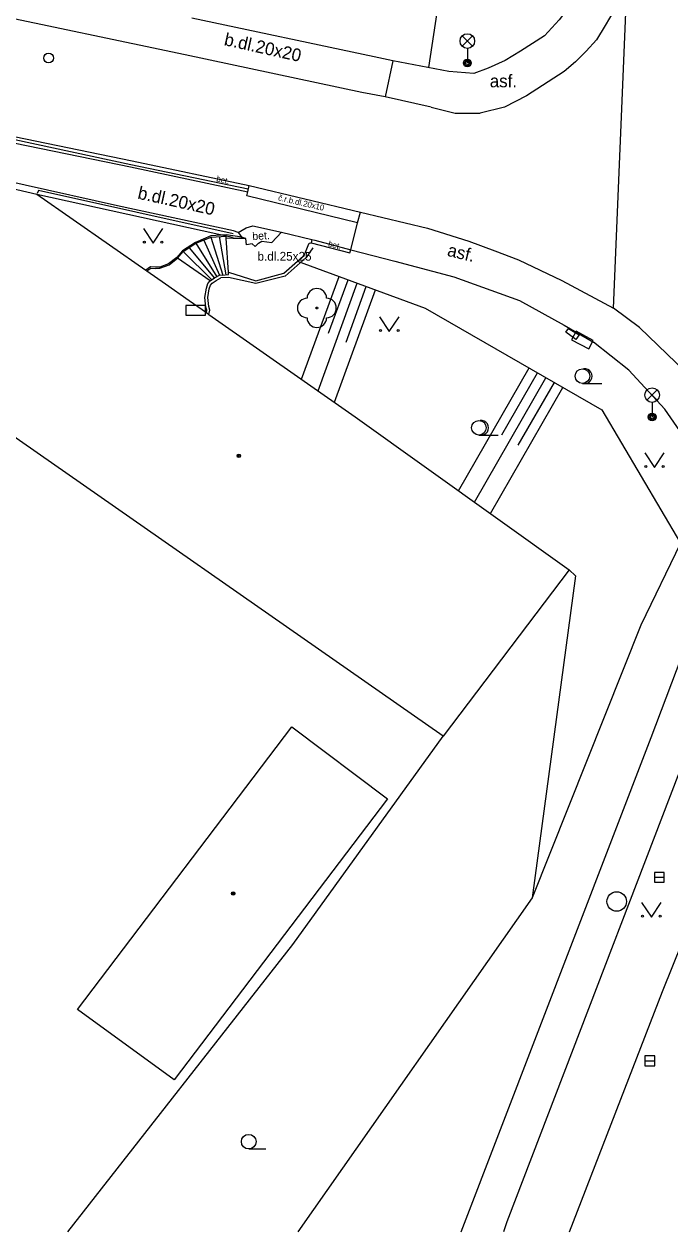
# Model space of a CAD drawing. Extents: x -595546 to -593986, y -1160845 to -1159202.
# Drawn here: x -594705.7 to -594672.6, y -1160843.2 to -1160781.2 of the extents above; entities that cross this region are included whole.
import ezdxf

# ---------------------------------------------------------------- set-up
doc = ezdxf.new("R2010")
doc.units = 0
for name, color, linetype in [('DOP - budovy nerozlisene - VP', 7, 'Continuous'), ('DOP - rozhrani ploch obecne', 7, 'Continuous'), ('Level 22', 7, 'Continuous'), ('Level 24', 7, 'Continuous'), ('Level 27', 7, 'Continuous'), ('Level 28', 7, 'Continuous'), ('Level 33', 7, 'Continuous'), ('Level 36', 7, 'Continuous'), ('Level 39', 7, 'Continuous'), ('silnoproud - povrch.  znaky a  RIS  skut. velikost', 7, 'Continuous'), ('Specificka linie pasportu komunikaci', 7, 'Continuous'), ('TM - budovy zdene_ betonove - VP', 7, 'Continuous'), ('TM - chodniky - VP', 7, 'Continuous'), ('TM - horni hrana svahu', 7, 'Continuous'), ('TM - komunikace - VP', 7, 'Continuous'), ('TM - plot drateny_ kovovy - VP', 7, 'Continuous'), ('TM - podezdivka plotu - VP', 7, 'Continuous'), ('TM - pomocna konstrukcni linie', 7, 'Continuous'), ('TM - popis povrchu', 7, 'Continuous'), ('TM - rozhrani mezi zpev. plochami mezi sebou - VP', 7, 'Continuous'), ('TM - rozhrani ploch obecne - VP', 7, 'Continuous'), ('TM - schody - VP', 7, 'Continuous'), ('TM - srafovani', 7, 'Continuous'), ('TM - zabradli - VP', 7, 'Continuous'), ('TM - zed operna - VP', 7, 'Continuous')]:
    doc.layers.add(name, color=color, linetype=linetype)

msp = doc.modelspace()

# ---------------------------------------------------------------- linework, layer by layer
at = {"layer": 'DOP - budovy nerozlisene - VP'}
for points in [[(-594702.99, -1160831.83), (-594691.98, -1160817.31)], [(-594691.98, -1160817.31), (-594687.07, -1160821.01)], [(-594687.07, -1160821.01), (-594698.03, -1160835.44)], [(-594698.03, -1160835.44), (-594702.99, -1160831.83)]]:
    msp.add_lwpolyline(points, dxfattribs=at)
at = {"layer": 'DOP - rozhrani ploch obecne'}
for points in [[(-594691.94, -1160828.49), (-594684.22, -1160817.79)], [(-594703.497, -1160843.241), (-594691.94, -1160828.49)]]:
    msp.add_lwpolyline(points, dxfattribs=at)
at = {"layer": 'Level 22'}
msp.add_circle((-594690.7, -1160795.81), 0.05, dxfattribs=at)
for centre, start, end in [((-594690.7, -1160795.31), 0, 180), ((-594691.2, -1160795.81), 90, 270), ((-594690.2, -1160795.81), 270, 90), ((-594690.7, -1160796.31), 180, 0)]:
    msp.add_arc(centre, 0.5, start, end, dxfattribs=at)
at = {"layer": 'Level 24'}
for points in [[(-594697.427, -1160796.178), (-594696.427, -1160796.178), (-594696.427, -1160795.678), (-594697.427, -1160795.678)], [(-594677.619, -1160797.447), (-594676.735, -1160797.915), (-594676.501, -1160797.473), (-594677.385, -1160797.005)]]:
    msp.add_lwpolyline(points, close=True, dxfattribs=at)
at = {"layer": 'Level 27'}
for p, q in [((-594673.36, -1160825.04), (-594672.86, -1160825.04)), ((-594673.85, -1160834.46), (-594673.35, -1160834.46))]:
    msp.add_line(p, q, dxfattribs=at)
for points in [[(-594673.36, -1160825.29), (-594672.86, -1160825.29), (-594672.86, -1160824.79), (-594673.36, -1160824.79)], [(-594673.85, -1160834.71), (-594673.35, -1160834.71), (-594673.35, -1160834.21), (-594673.85, -1160834.21)]]:
    msp.add_lwpolyline(points, close=True, dxfattribs=at)
msp.add_circle((-594675.3, -1160826.28), 0.5, dxfattribs=at)
at = {"layer": 'Level 28'}
msp.add_circle((-594704.48, -1160782.98), 0.25, dxfattribs=at)
at = {"layer": 'Level 33'}
for p, q in [((-594683.235, -1160782.37), (-594682.705, -1160781.84)), ((-594683.235, -1160781.84), (-594682.705, -1160782.37)), ((-594682.97, -1160782.48), (-594682.97, -1160783.23)), ((-594673.745, -1160800.55), (-594673.215, -1160800.02)), ((-594673.745, -1160800.02), (-594673.215, -1160800.55)), ((-594673.48, -1160800.66), (-594673.48, -1160801.41))]:
    msp.add_line(p, q, dxfattribs=at)
for centre, radius in [((-594682.97, -1160782.105), 0.375), ((-594682.97, -1160783.23), 0.2), ((-594682.97, -1160783.23), 0.145), ((-594682.97, -1160783.23), 0.0876), ((-594673.48, -1160800.285), 0.375), ((-594673.48, -1160801.41), 0.2), ((-594673.48, -1160801.41), 0.145), ((-594673.48, -1160801.41), 0.0876)]:
    msp.add_circle(centre, radius, dxfattribs=at)
at = {"layer": 'Level 36'}
for p, q in [((-594677.06, -1160799.685), (-594676.06, -1160799.685)), ((-594682.38, -1160802.335), (-594681.38, -1160802.335)), ((-594694.2, -1160838.985), (-594693.325, -1160838.985))]:
    msp.add_line(p, q, dxfattribs=at)
for points in [[(-594699.61, -1160791.73), (-594699.11, -1160792.48), (-594698.61, -1160791.73)], [(-594687.48, -1160796.27), (-594686.98, -1160797.02), (-594686.48, -1160796.27)], [(-594673.86, -1160803.25), (-594673.36, -1160804), (-594672.86, -1160803.25)], [(-594674.02, -1160826.33), (-594673.52, -1160827.08), (-594673.02, -1160826.33)]]:
    msp.add_lwpolyline(points, dxfattribs=at)
for centre, radius in [((-594699.56, -1160792.43), 0.05), ((-594698.661, -1160792.43), 0.05), ((-594687.43, -1160796.97), 0.05), ((-594686.531, -1160796.97), 0.05), ((-594677.06, -1160799.31), 0.375), ((-594682.38, -1160801.96), 0.375), ((-594673.81, -1160803.95), 0.05), ((-594672.911, -1160803.95), 0.05), ((-594673.97, -1160827.03), 0.05), ((-594673.071, -1160827.03), 0.05), ((-594694.2, -1160838.61), 0.375)]:
    msp.add_circle(centre, radius, dxfattribs=at)
for centre in [(-594676.935, -1160799.31), (-594682.255, -1160801.96)]:
    msp.add_arc(centre, 0.375, 260.40593, 99.59407, dxfattribs=at)
at = {"layer": 'Level 39'}
for centre, radius in [((-594694.71, -1160803.4), 0.09), ((-594694.71, -1160803.4), 0.0398), ((-594695, -1160825.87), 0.09), ((-594695, -1160825.87), 0.0398)]:
    msp.add_circle(centre, radius, dxfattribs=at)
at = {"layer": 'silnoproud - povrch.  znaky a  RIS  skut. velikost'}
msp.add_lwpolyline([(-594677.22, -1160797.19), (-594677.4, -1160797.42), (-594677.92, -1160797.06), (-594677.78, -1160796.86), (-594677.22, -1160797.19)], dxfattribs=at)
at = {"layer": 'Specificka linie pasportu komunikaci'}
msp.add_lwpolyline([(-594675.46, -1160795.82), (-594674.78, -1160779.4)], dxfattribs=at)
at = {"layer": 'TM - budovy zdene_ betonove - VP'}
for points in [[(-594706.91, -1160789.54), (-594705.09, -1160789.97)], [(-594705.09, -1160789.97), (-594699.49, -1160793.87), (-594699.44, -1160793.91)], [(-594699.44, -1160793.91), (-594698.48, -1160794.57)], [(-594698.48, -1160794.57), (-594697.26, -1160795.42), (-594696.37, -1160796.04)], [(-594696.37, -1160796.04), (-594696.24, -1160796.14), (-594688.74, -1160801.4), (-594677.74, -1160809.25)], [(-594684.22, -1160817.79), (-594709.11, -1160800.44)], [(-594677.74, -1160809.25), (-594684.22, -1160817.79)]]:
    msp.add_lwpolyline(points, dxfattribs=at)
at = {"layer": 'TM - chodniky - VP'}
for points in [[(-594677.57, -1160780.13), (-594678.26, -1160781.01), (-594679.01, -1160781.84), (-594680.24, -1160782.63)], [(-594687.75, -1160782.92), (-594697.12, -1160780.93)], [(-594680.24, -1160782.63), (-594681.03, -1160783.1), (-594681.91, -1160783.49)], [(-594686.79, -1160783.12), (-594687.75, -1160782.92)], [(-594683.93, -1160783.67), (-594686.79, -1160783.12)], [(-594682.63, -1160783.78), (-594683.93, -1160783.67)], [(-594681.91, -1160783.49), (-594682.63, -1160783.78)], [(-594694.75, -1160791.94), (-594694.33, -1160791.7)], [(-594694.33, -1160791.7), (-594693.98, -1160791.6)], [(-594693.98, -1160791.6), (-594692.52, -1160791.91)], [(-594692.52, -1160791.91), (-594690.95, -1160792.3)], [(-594690.95, -1160792.3), (-594690.81, -1160792.33)], [(-594690.81, -1160792.33), (-594688.96, -1160792.82)], [(-594688.96, -1160792.82), (-594686.7, -1160793.4)], [(-594686.7, -1160793.4), (-594683.66, -1160794.21)], [(-594683.66, -1160794.21), (-594680.29, -1160795.43)], [(-594680.29, -1160795.43), (-594678, -1160796.69)], [(-594678, -1160796.69), (-594676.49, -1160797.56)], [(-594674.67, -1160799.01), (-594676.49, -1160797.56)], [(-594672.82, -1160801), (-594674.67, -1160799.01)], [(-594671.4, -1160803.05), (-594672.82, -1160801)], [(-594669.62, -1160813.23), (-594680.94, -1160842.73)], [(-594673.53, -1160817.86), (-594671.69, -1160813.02)], [(-594683.291, -1160843.241), (-594673.53, -1160817.86)], [(-594680.94, -1160842.73), (-594681.117, -1160843.241)]]:
    msp.add_lwpolyline(points, dxfattribs=at)
at = {"layer": 'TM - horni hrana svahu'}
msp.add_lwpolyline([(-594691.7, -1160793.41), (-594685.13, -1160795.82), (-594676.07, -1160801.04), (-594672.03, -1160807.88), (-594674.06, -1160812.09)], dxfattribs=at)
at = {"layer": 'TM - komunikace - VP'}
for points in [[(-594674.78, -1160779.4), (-594675.9, -1160781.31)], [(-594697.47, -1160782.82), (-594707.9, -1160780.62)], [(-594675.9, -1160781.31), (-594676.34, -1160782.05)], [(-594676.34, -1160782.05), (-594676.86, -1160782.63), (-594677.41, -1160783.17), (-594678, -1160783.67)], [(-594688.39, -1160784.74), (-594697.47, -1160782.82)], [(-594678, -1160783.67), (-594679.94, -1160784.91)], [(-594687.2, -1160784.97), (-594688.39, -1160784.74)], [(-594684.83, -1160785.5), (-594687.2, -1160784.97)], [(-594679.94, -1160784.91), (-594681.07, -1160785.5), (-594682.31, -1160785.81)], [(-594684.83, -1160785.5), (-594683.59, -1160785.81)], [(-594710.08, -1160786.22), (-594700.18, -1160788.26)], [(-594683.59, -1160785.81), (-594682.55, -1160785.81), (-594682.31, -1160785.81)], [(-594700.18, -1160788.26), (-594694.17, -1160789.52)], [(-594694.17, -1160789.52), (-594688.46, -1160790.89)], [(-594688.46, -1160790.89), (-594685.02, -1160791.72)], [(-594685.02, -1160791.72), (-594682.9, -1160792.38)], [(-594682.9, -1160792.38), (-594681.56, -1160792.88), (-594680.34, -1160793.33)], [(-594680.34, -1160793.33), (-594678.12, -1160794.4)], [(-594678.12, -1160794.4), (-594675.46, -1160795.82)], [(-594674.13, -1160796.81), (-594675.46, -1160795.82)], [(-594670.84, -1160799.98), (-594674.13, -1160796.81)], [(-594672.95, -1160830.91), (-594667.81, -1160818.16)], [(-594677.729, -1160843.241), (-594672.95, -1160830.91)]]:
    msp.add_lwpolyline(points, dxfattribs=at)
at = {"layer": 'TM - plot drateny_ kovovy - VP'}
for points in [[(-594677.74, -1160809.25), (-594677.41, -1160809.56)], [(-594677.41, -1160809.56), (-594679.65, -1160826.1)], [(-594679.65, -1160826.1), (-594691.669, -1160843.241)]]:
    msp.add_lwpolyline(points, dxfattribs=at)
at = {"layer": 'TM - podezdivka plotu - VP'}
for points in [[(-594705.09, -1160789.97), (-594695.04, -1160792.18)], [(-594694.25, -1160789.84), (-594694.17, -1160789.52)], [(-594695.04, -1160792.18), (-594695, -1160792.24)]]:
    msp.add_lwpolyline(points, dxfattribs=at)
at = {"layer": 'TM - pomocna konstrukcni linie'}
msp.add_lwpolyline([(-594674.06, -1160812.09), (-594679.65, -1160826.1)], dxfattribs=at)
at = {"layer": 'TM - rozhrani mezi zpev. plochami mezi sebou - VP'}
for points in [[(-594686.79, -1160783.12), (-594687.2, -1160784.97)], [(-594694.3, -1160790.05), (-594694.25, -1160789.84)], [(-594694.3, -1160790.05), (-594694.25, -1160789.84)], [(-594688.61, -1160791.43), (-594694.3, -1160790.05)], [(-594688.61, -1160791.43), (-594688.46, -1160790.89)], [(-594688.96, -1160792.82), (-594688.61, -1160791.43)], [(-594690.95, -1160792.3), (-594690.99, -1160792.46)]]:
    msp.add_lwpolyline(points, dxfattribs=at)
at = {"layer": 'TM - rozhrani ploch obecne - VP'}
for points in [[(-594692.52, -1160791.91), (-594693.01, -1160792.44)], [(-594697.56, -1160792.91), (-594696.91, -1160792.49)], [(-594696.91, -1160792.49), (-594696.13, -1160792.17)], [(-594696.13, -1160792.17), (-594695.36, -1160792.12)], [(-594695.35, -1160792.23), (-594695.36, -1160792.12)], [(-594695.24, -1160793.97), (-594695.35, -1160792.23)], [(-594695, -1160792.24), (-594695.35, -1160792.23)], [(-594694.5, -1160792.25), (-594695, -1160792.24)], [(-594694.35, -1160792.25), (-594694.5, -1160792.25)], [(-594694.31, -1160792.56), (-594694.35, -1160792.25)], [(-594694.03, -1160792.52), (-594694.31, -1160792.56)], [(-594693.87, -1160792.66), (-594694.03, -1160792.52)], [(-594693.87, -1160792.66), (-594693.7, -1160792.48)], [(-594693.7, -1160792.48), (-594693.53, -1160792.38)], [(-594693.53, -1160792.38), (-594693.01, -1160792.44)], [(-594691.15, -1160792.61), (-594691.09, -1160792.48)], [(-594691.09, -1160792.48), (-594690.99, -1160792.46)], [(-594690.99, -1160792.46), (-594689, -1160792.98)], [(-594697.85, -1160793.26), (-594697.56, -1160792.91)], [(-594691.7, -1160793.41), (-594691.36, -1160793.12)], [(-594691.36, -1160793.12), (-594691.15, -1160792.61)], [(-594689, -1160792.98), (-594688.96, -1160792.82)], [(-594699.44, -1160793.91), (-594699.23, -1160793.76)], [(-594699.23, -1160793.76), (-594698.98, -1160793.78)], [(-594698.98, -1160793.78), (-594698.76, -1160793.77)], [(-594698.76, -1160793.77), (-594698.29, -1160793.6)], [(-594698.29, -1160793.6), (-594697.85, -1160793.26)], [(-594696.18, -1160794.42), (-594697.85, -1160793.26)], [(-594692.4, -1160794.03), (-594691.7, -1160793.41)], [(-594696.18, -1160794.42), (-594695.95, -1160794.27)], [(-594695.95, -1160794.27), (-594695.67, -1160794.11)], [(-594695.67, -1160794.11), (-594695.57, -1160794.13)], [(-594695.57, -1160794.13), (-594695.23, -1160794.09)], [(-594695.24, -1160793.97), (-594693.83, -1160794.41)], [(-594695.23, -1160794.09), (-594695.24, -1160793.97)], [(-594693.83, -1160794.41), (-594692.4, -1160794.03)], [(-594696.45, -1160795.27), (-594696.37, -1160794.79)], [(-594696.37, -1160794.79), (-594696.3, -1160794.56)], [(-594696.3, -1160794.56), (-594696.18, -1160794.42)], [(-594696.4, -1160795.76), (-594696.45, -1160795.27)], [(-594696.35, -1160795.93), (-594696.4, -1160795.76)], [(-594696.37, -1160796.04), (-594696.35, -1160795.93)]]:
    msp.add_lwpolyline(points, dxfattribs=at)
at = {"layer": 'TM - schody - VP'}
for points in [[(-594696.91, -1160792.49), (-594695.84, -1160794.21)], [(-594696.51, -1160792.32), (-594695.7, -1160794.13)], [(-594696.14, -1160792.17), (-594695.53, -1160794.13)], [(-594695.72, -1160792.14), (-594695.38, -1160794.11)], [(-594697.56, -1160792.91), (-594696.09, -1160794.36)], [(-594697.26, -1160792.72), (-594695.96, -1160794.28)]]:
    msp.add_lwpolyline(points, dxfattribs=at)
at = {"layer": 'TM - srafovani'}
for points in [[(-594684.08, -1160777.57), (-594684.96, -1160783.47)], [(-594691.49, -1160799.47), (-594689.56, -1160794.2)], [(-594690.1, -1160797.1), (-594689.09, -1160794.37)], [(-594690.64, -1160800.07), (-594688.63, -1160794.54)], [(-594689.8, -1160800.65), (-594687.69, -1160794.88)], [(-594689.2, -1160797.57), (-594688.16, -1160794.71)], [(-594683.43, -1160805.19), (-594679.8, -1160798.89)], [(-594681.2, -1160802.32), (-594679.37, -1160799.14)], [(-594682.61, -1160805.78), (-594678.94, -1160799.39)], [(-594681.79, -1160806.36), (-594678.07, -1160799.89)], [(-594680.36, -1160802.86), (-594678.5, -1160799.64)]]:
    msp.add_lwpolyline(points, dxfattribs=at)
at = {"layer": 'TM - zabradli - VP'}
for points in [[(-594710.2, -1160786.31), (-594700.25, -1160788.44)], [(-594700.25, -1160788.44), (-594694.22, -1160789.69)], [(-594705, -1160789.77), (-594705.06, -1160789.94)], [(-594695, -1160792), (-594705, -1160789.77)], [(-594694.55, -1160792.17), (-594695.36, -1160792.06), (-594696.14, -1160792.11), (-594696.94, -1160792.44), (-594697.6, -1160792.87), (-594697.89, -1160793.22), (-594698.32, -1160793.55), (-594698.77, -1160793.71), (-594698.98, -1160793.72), (-594699.25, -1160793.7), (-594699.49, -1160793.87)], [(-594694.36, -1160792.24), (-594694.55, -1160792.17)], [(-594690.9, -1160792.72), (-594691.25, -1160793.22), (-594692.33, -1160794.17)], [(-594696.24, -1160796.14), (-594696.2, -1160795.92), (-594696.25, -1160795.73), (-594696.3, -1160795.28), (-594696.23, -1160794.82), (-594696.17, -1160794.63), (-594696.08, -1160794.53), (-594695.87, -1160794.4), (-594695.63, -1160794.26)], [(-594692.33, -1160794.17), (-594693.83, -1160794.56), (-594695.24, -1160794.24), (-594695.63, -1160794.26)]]:
    msp.add_lwpolyline(points, dxfattribs=at)
at = {"layer": 'TM - zed operna - VP'}
for points in [[(-594710.21, -1160786.52), (-594700.28, -1160788.56)], [(-594700.94, -1160790.56), (-594715.18, -1160787.38)], [(-594700.28, -1160788.56), (-594694.25, -1160789.84)], [(-594694.98, -1160791.85), (-594700.94, -1160790.56)], [(-594694.75, -1160791.94), (-594694.98, -1160791.85)], [(-594694.7, -1160791.96), (-594694.75, -1160791.94)], [(-594694.5, -1160792.25), (-594694.7, -1160791.96)]]:
    msp.add_lwpolyline(points, dxfattribs=at)

# ---------------------------------------------------------------- texts
at = {"layer": 'TM - popis povrchu'}
for s, height, rotation, p in [('b.dl.20x20', 0.65, 347.46685, (-594695.5, -1160782.31)), ('bet.', 0.3, 348, (-594695.88, -1160789.31)), ('b.dl.20x20', 0.65, 347.46685, (-594699.94, -1160790.19)), ('č.r.b.dl.20x10', 0.3, 347, (-594692.71, -1160790.28)), ('bet.', 0.4, 3.70537, (-594694, -1160792.33)), ('bet.', 0.3, 345, (-594690.14, -1160792.64)), ('asf.', 0.65, 346.68392, (-594684.04, -1160793.13))]:
    msp.add_text(s, height=height, rotation=rotation, dxfattribs=at).set_placement(p)
for s, height, p in [('asf.', 0.65, (-594681.82, -1160784.48)), ('b.dl.25x25', 0.45, (-594693.75, -1160793.38))]:
    msp.add_text(s, height=height, dxfattribs=at).set_placement(p)

doc.saveas('drawing.dxf')
